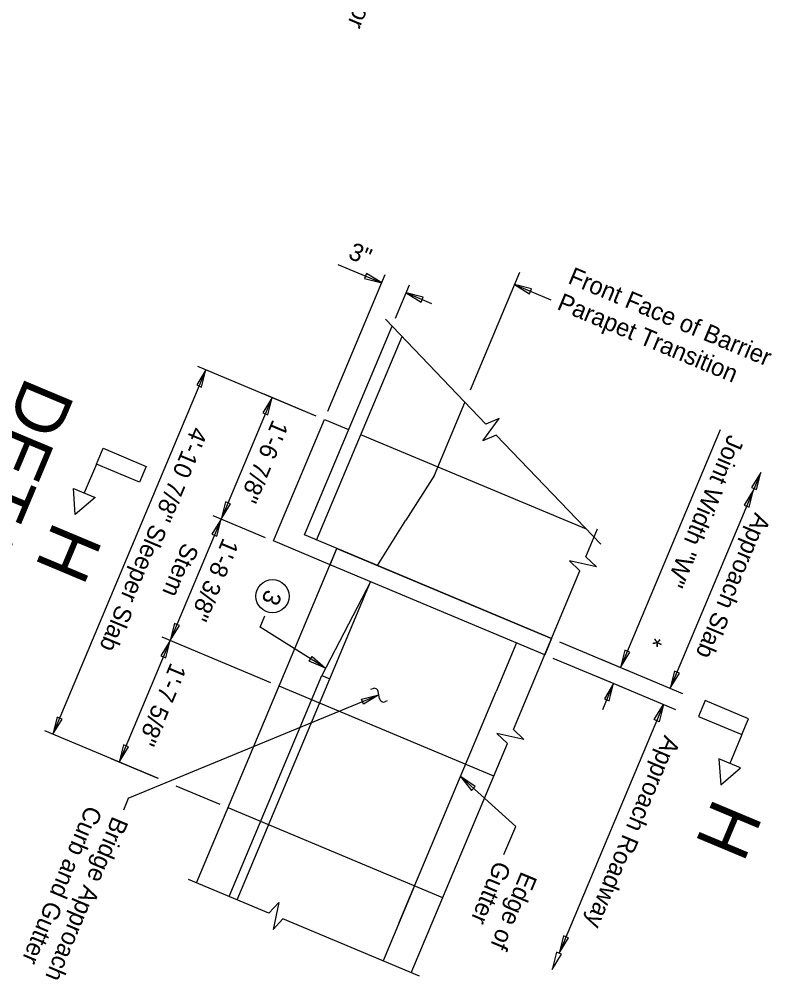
# Model space of a CAD drawing. Extents: x 1968564 to 1968711, y 796599 to 796794.
# Drawn here: x 1968596.99 to 1968618.4, y 796657.43 to 796684.77 of the extents above; entities that cross this region are included whole.
import ezdxf

# ---------------------------------------------------------------- set-up
doc = ezdxf.new("R2010")
doc.units = 0
for name, color, linetype in [('BR_AUTO DIMENSION', 7, 'Continuous'), ('BR_CONCRETE', 7, 'Continuous'), ('BR_DETAILS', 7, 'Continuous'), ('BR_TABLE LINES', 7, 'Continuous'), ('BR_TEXT', 7, 'Continuous')]:
    doc.layers.add(name, color=color, linetype=linetype)

msp = doc.modelspace()

# ---------------------------------------------------------------- linework, layer by layer
at = {"layer": 'BR_AUTO DIMENSION'}
for p, q in [((1968606.058, 796677.789), (1968607.305, 796677.266)), ((1968605.769, 796673.606), (1968607.401, 796677.497)), ((1968611.222, 796677.558), (1968609.817, 796674.207)), ((1968607.696, 796676.26), (1968608.093, 796677.207)), ((1968611.079, 796677.217), (1968612.114, 796676.783)), ((1968608.734, 796676.667), (1968607.996, 796676.976)), ((1968602.304, 796674.788), (1968597.953, 796664.414)), ((1968605.442, 796673.472), (1968602.074, 796674.885)), ((1968604.189, 796673.998), (1968602.739, 796670.54)), ((1968605.442, 796673.472), (1968603.959, 796674.094)), ((1968616.929, 796673.076), (1968614.095, 796666.319)), ((1968618.088, 796671.867), (1968615.512, 796665.724)), ((1968602.739, 796670.54), (1968601.288, 796667.081)), ((1968604.001, 796670.01), (1968602.508, 796670.636)), ((1968603.845, 796667.459), (1968603.982, 796667.785)), ((1968605.708, 796666.298), (1968603.845, 796667.459)), ((1968604.155, 796665.879), (1968601.058, 796667.178)), ((1968604.155, 796665.879), (1968601.058, 796667.178)), ((1968601.288, 796667.081), (1968599.838, 796663.623)), ((1968611.138, 796667.015), (1968611.14, 796667.016)), ((1968612.366, 796667.044), (1968614.326, 796666.222)), ((1968612.173, 796666.583), (1968614.132, 796665.761)), ((1968613.47, 796666.581), (1968615.858, 796665.579)), ((1968613.431, 796666.055), (1968615.664, 796665.118)), ((1968613.593, 796665.12), (1968613.902, 796665.857)), ((1968600.092, 796662.601), (1968607.222, 796665.535)), ((1968615.318, 796665.263), (1968612.35, 796658.186)), ((1968600.952, 796663.156), (1968597.723, 796664.51)), ((1968600.946, 796663.159), (1968599.607, 796663.72)), ((1968611.117, 796661.79), (1968609.542, 796663.21)), ((1968602.705, 796662.421), (1968601.462, 796662.942)), ((1968600.096, 796662.59), (1968599.957, 796662.258)), ((1968610.781, 796660.989), (1968611.117, 796661.79))]:
    msp.add_line(p, q, dxfattribs=at)
for points in [[(1968606.814, 796677.39), (1968607.305, 796677.266), (1968606.872, 796677.529)], [(1968611.569, 796677.092), (1968611.079, 796677.217), (1968611.511, 796676.954)], [(1968608.486, 796676.852), (1968607.996, 796676.976), (1968608.428, 796676.714)], [(1968602.18, 796674.298), (1968602.304, 796674.788), (1968602.042, 796674.356)], [(1968604.065, 796673.508), (1968604.189, 796673.998), (1968603.927, 796673.566)], [(1968617.964, 796671.377), (1968618.088, 796671.867), (1968617.826, 796671.435)], [(1968617.756, 796670.882), (1968617.88, 796671.372), (1968617.618, 796670.94)], [(1968602.863, 796671.03), (1968602.739, 796670.54), (1968603.001, 796670.972)], [(1968602.614, 796670.049), (1968602.739, 796670.54), (1968602.476, 796670.107)], [(1968601.412, 796667.571), (1968601.288, 796667.081), (1968601.551, 796667.513)], [(1968601.164, 796666.591), (1968601.288, 796667.081), (1968601.026, 796666.649)], [(1968605.323, 796666.626), (1968605.708, 796666.298), (1968605.244, 796666.499)], [(1968614.22, 796666.809), (1968614.095, 796666.319), (1968614.358, 796666.751)], [(1968615.636, 796666.215), (1968615.512, 796665.724), (1968615.774, 796666.157)], [(1968613.778, 796665.367), (1968613.902, 796665.857), (1968613.639, 796665.425)], [(1968606.731, 796665.414), (1968607.222, 796665.535), (1968606.788, 796665.276)], [(1968615.056, 796664.831), (1968615.318, 796665.263), (1968615.194, 796664.773)], [(1968598.077, 796664.904), (1968597.953, 796664.414), (1968598.216, 796664.846)], [(1968599.962, 796664.113), (1968599.838, 796663.623), (1968600.1, 796664.055)], [(1968609.964, 796662.931), (1968609.542, 796663.21), (1968609.863, 796662.819)], [(1968612.474, 796658.676), (1968612.35, 796658.186), (1968612.613, 796658.618)], [(1968612.28, 796658.212), (1968612.155, 796657.722), (1968612.418, 796658.154)]]:
    msp.add_lwpolyline(points, close=True, dxfattribs=at)
msp.add_circle((1968604.197, 796668.344), 0.472, dxfattribs=at)
at = {"layer": 'BR_CONCRETE'}
for p, q in [((1968605.107, 796670.088), (1968607.599, 796676.029)), ((1968606.275, 796671.903), (1968607.882, 796675.734)), ((1968608.804, 796671.791), (1968609.672, 796673.862)), ((1968604.416, 796670.378), (1968605.673, 796673.375)), ((1968605.673, 796673.375), (1968606.364, 796673.085)), ((1968613.127, 796670.249), (1968606.71, 796672.94)), ((1968605.453, 796669.943), (1968606.275, 796671.903)), ((1968608.804, 796671.791), (1968607.993, 796670.505)), ((1968607.182, 796669.218), (1968607.993, 796670.505)), ((1968612.136, 796667.14), (1968605.107, 796670.088)), ((1968602.04, 796660.19), (1968606.029, 796669.702)), ((1968606.029, 796669.702), (1968607.182, 796669.218)), ((1968611.942, 796666.679), (1968605.836, 796669.24)), ((1968603.193, 796659.706), (1968606.989, 796668.757)), ((1968606.989, 796668.757), (1968605.598, 796666.087)), ((1968611.139, 796667.016), (1968610.558, 796665.633)), ((1968602.962, 796659.803), (1968605.598, 796666.087)), ((1968605.598, 796666.087), (1968605.828, 796665.99)), ((1968610.492, 796663.221), (1968604.386, 796665.782)), ((1968607.799, 796659.054), (1968610.558, 796665.633)), ((1968609.042, 796659.763), (1968602.935, 796662.324)), ((1968608.238, 796660.1), (1968607.343, 796657.966))]:
    msp.add_line(p, q, dxfattribs=at)
msp.add_lwpolyline([(1968605.836, 796669.24), (1968604.222, 796669.917), (1968604.416, 796670.378)], dxfattribs=at)
at = {"layer": 'BR_DETAILS'}
for p, q in [((1968607.408, 796676.229), (1968610.263, 796673.244)), ((1968610.563, 796672.93), (1968613.533, 796669.825)), ((1968613.11, 796669.464), (1968613.447, 796670.266)), ((1968611.049, 796664.55), (1968612.943, 796669.064)), ((1968607.051, 796665.712), (1968606.987, 796665.688)), ((1968607.245, 796665.435), (1968607.199, 796665.635)), ((1968607.458, 796665.363), (1968607.411, 796665.344)), ((1968608.146, 796657.629), (1968610.881, 796664.15)), ((1968604.096, 796659.328), (1968601.81, 796660.286)), ((1968608.377, 796657.532), (1968604.496, 796659.16))]:
    msp.add_line(p, q, dxfattribs=at)
for points in [[(1968610.563, 796672.93), (1968610.184, 796672.768), (1968610.642, 796673.406), (1968610.263, 796673.244)], [(1968613.11, 796669.464), (1968613.41, 796669.182), (1968612.643, 796669.347), (1968612.943, 796669.064)], [(1968611.049, 796664.55), (1968611.349, 796664.267), (1968610.582, 796664.433), (1968610.881, 796664.15)], [(1968604.096, 796659.328), (1968604.378, 796659.627), (1968604.213, 796658.86), (1968604.496, 796659.16)]]:
    msp.add_lwpolyline(points, dxfattribs=at)
for centre, radius, start, end in [((1968607.098, 796665.62), 0.103, 8.9468, 117.2324), ((1968607.36, 796665.448), 0.116, 186.502, 296.3009)]:
    msp.add_arc(centre, radius, start, end, dxfattribs=at)
at = {"layer": 'BR_TABLE LINES'}
for p, q in [((1968599.189, 796672.105), (1968598.845, 796671.285)), ((1968617.549, 796664.408), (1968617.206, 796663.588))]:
    msp.add_line(p, q, dxfattribs=at)
for points in [[(1968600.608, 796672.04), (1968600.419, 796671.589), (1968599.189, 796672.105), (1968599.378, 796672.556)], [(1968599.153, 796671.156), (1968598.588, 796670.67), (1968598.538, 796671.414)], [(1968605.836, 796669.24), (1968606.029, 796669.702), (1968612.136, 796667.14), (1968611.942, 796666.679)], [(1968616.509, 796665.375), (1968616.32, 796664.924), (1968617.549, 796664.408), (1968617.739, 796664.859)], [(1968616.898, 796663.717), (1968616.948, 796662.974), (1968617.513, 796663.459)]]:
    msp.add_lwpolyline(points, close=True, dxfattribs=at)

# ---------------------------------------------------------------- texts
at = {"layer": 'BR_AUTO DIMENSION'}
for s, rotation, p in [('3"', 337.246, (1968606.322, 796677.971)), ('4\'-10 7/8" Sleeper Slab', 247.246, (1968601.909, 796673.2)), ('1\'-6 7/8"', 247.246, (1968604.207, 796673.395)), ('Joint Width "W"', 247.246, (1968617.169, 796672.97)), ('1\'-8 3/8"', 247.246, (1968602.795, 796670.028)), ('1\'-7 5/8"', 247.246, (1968601.306, 796666.478))]:
    msp.add_text(s, height=0.5, rotation=rotation, dxfattribs=at).set_placement(p)
at = {"layer": 'BR_TEXT'}
for s, height, rotation, p in [('Place Geotextile for ', 0.49995, 247.246, (1968608.571, 796690.009)), ('Front Face of Barrier', 0.49995, 337.246, (1968612.573, 796677.263)), ('Parapet Transition', 0.49995, 337.246, (1968612.263, 796676.525)), ('DETAIL "B"', 1.5, 247.246, (1968597.198, 796674.631)), ('Approach Slab', 0.49995, 247.246, (1968617.923, 796670.748)), ('H', 1.5, 247.246, (1968597.993, 796670.519)), ('Stem', 0.5, 247.246, (1968601.655, 796669.895)), ('3', 0.5, 247.246, (1968604.018, 796668.564)), ('*', 0.5, 247.246, (1968614.852, 796667.284)), ('Approach Roadway', 0.49995, 247.246, (1968615.35, 796664.409)), ('H', 1.5, 247.246, (1968616.768, 796662.648)), ('Curb and Gutter', 0.49995, 247.246, (1968598.913, 796662.417)), ('Bridge Approach', 0.49995, 247.246, (1968599.651, 796662.108)), ('Gutter', 0.4999, 247.246, (1968610.541, 796660.845)), ('Edge of', 0.4999, 247.246, (1968611.279, 796660.536))]:
    msp.add_text(s, height=height, rotation=rotation, dxfattribs=at).set_placement(p)

doc.saveas('drawing.dxf')
